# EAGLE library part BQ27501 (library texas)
System-Side Impedance Track? Fuel Gauge Source: bq27500-v100.pdf
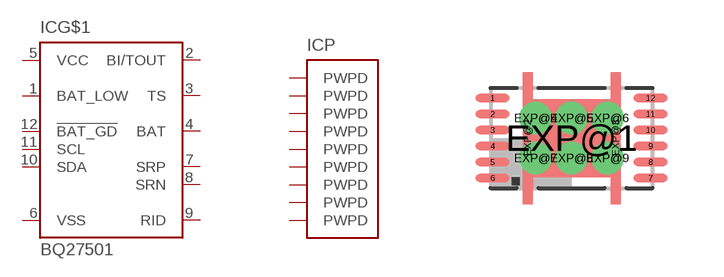
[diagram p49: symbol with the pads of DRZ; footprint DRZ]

Designator prefix IC; gates G$1=BQ27501 P=PWPD9

## BQ27501 (MPN: BQ27501DRZT; OC_FARNELL: 1710789; OC_NEWARK: 50P9379)  [DRZ]
1  G$1:BAT_LOW  out
2  G$1:BI/TOUT
3  G$1:TS  in
4  G$1:BAT  in
5  G$1:VCC  pwr
6  G$1:VSS  pwr
7  G$1:SRP  in
8  G$1:SRN  in
9  G$1:RID  in
10  G$1:SDA
11  G$1:SCL  in
12  G$1:!BAT_GD  out
EXP@1  P:PWPD  pwr
EXP@2  P:PWPD  pwr
EXP@3  P:PWPD  pwr
EXP@4  P:PWPD  pwr
EXP@5  P:PWPD  pwr
EXP@6  P:PWPD  pwr
EXP@7  P:PWPD  pwr
EXP@8  P:PWPD  pwr
EXP@9  P:PWPD  pwr

## Footprint DRZ (pad centres in mm)
DRZ (S-PDSO-N12) PLASTIC SMALL OUTLINE Source: bq27500-v100.pdf
smd 0.85 x 0.2: 1 -1.975,1; 2 -1.975,0.6; 3 -1.975,0.2; 4 -1.975,-0.2; 5 -1.975,-0.6; 6 -1.975,-1; 7 1.975,-1; 8 1.975,-0.6; 9 1.975,-0.2; 10 1.975,0.2; 11 1.975,0.6; 12 1.975,1
smd 2.45 x 1.95: EXP@1 0,0
smd 0.25 x 3.3: EXP@2 -1.1,0; EXP@3 1.1,0
drill 0.3 pad 0.406 round: EXP@4 -0.9,0.5; EXP@5 0,0.5; EXP@6 0.9,0.5; EXP@7 -0.9,-0.5; EXP@8 0,-0.5; EXP@9 0.9,-0.5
